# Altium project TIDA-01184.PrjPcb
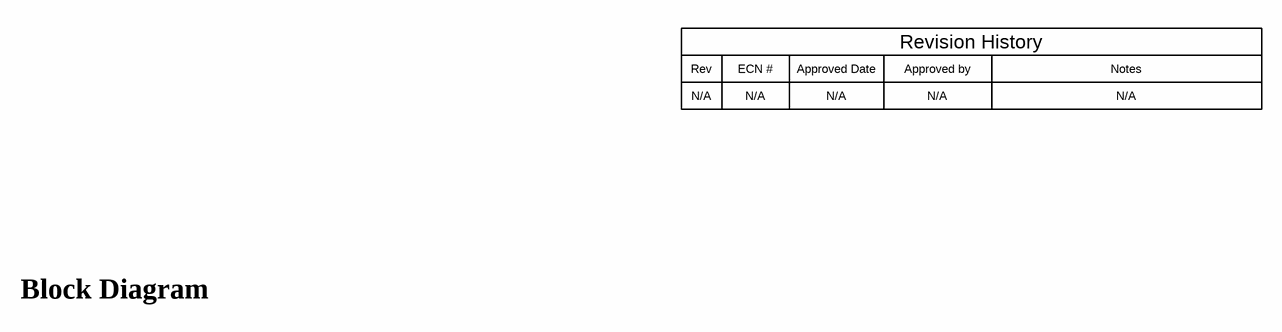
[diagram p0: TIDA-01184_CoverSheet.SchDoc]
CopyrightYear: 2017; PCB_Rev: A; PRJ_Customer: Public Release; PRJ_Engineer: Mitchell Kinkeade; PRJ_Number: TIDA-01184; PRJ_Title: Smart Power Switch Seat Heater Reference Design; SCH_Rev: A; TechSupport: http://www.ti.com/support; TID: TIDA-01184
7 sheets, 128 parts. Net scope: flat (ports and power ports of the same name join across sheets).
Board file: TIDA-01184_Mainboard.PcbDoc
Sheets:
  TIDA-01184_CoverSheet.SchDoc
  TIDA-01184_LED_Drivers.SchDoc
  TIDA-01184_Digital.SchDoc
  TIDA-01184_EVM_Hardware.SchDoc
  TIDA-01184_HighSideDrivers.SchDoc
  TIDA-01184_Load_Card.SchDoc
  TIDA-01184_Power.SchDoc

## Sheet TIDA-01184_CoverSheet.SchDoc
size 431 x 279 mm; Date: Not shown in title block; ApprovedBy: Not shown in title block; CheckedBy: Not shown in title block; Author: Not shown in title block; CompanyName: Not shown in title block; Engineer: Not shown in title block; Organization: Not shown in title block; Address1: Not shown in title block; Address2: Not shown in title block; Address3: Not shown in title block; Address4: Not shown in title block; DocumentNumber: 1; Revision: Use project parameter SCH_Rev; SheetNumber: 1; SheetTotal: 3; PageSetup: Record=PageOptions¦CenterHorizontal=True¦CenterVertical=True¦PrintScale=1.00¦XCorrection=1.00¦YCorrection=1.00¦PrintKind=0¦BorderSize=5000000¦LeftOffset=0¦BottomOffset=0¦Orientation=2¦PaperLength=1000¦PaperWidth=1000¦Scale=100¦PaperSource=15¦PrintQuality=600¦MediaType=1¦DitherType=10¦PaperKind=Letter¦PrintScaleMode=1

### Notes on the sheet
- Rev
- N/A
- ECN #
- Approved Date
- Approved by
- Revision History
- Notes
- Block Diagram

## Sheet TIDA-01184_LED_Drivers.SchDoc
size 431 x 279 mm; Date: Not shown in title block; ApprovedBy: Not shown in title block; CheckedBy: Not shown in title block; Author: Not shown in title block; CompanyName: Not shown in title block; Engineer: Not shown in title block; Organization: Not shown in title block; Address1: Not shown in title block; Address2: Not shown in title block; Address3: Not shown in title block; Address4: Not shown in title block; DocumentNumber: 1; Revision: Use project parameter SCH_Rev; SheetNumber: 2; SheetTotal: 3; PageSetup: Record=PageOptions¦CenterHorizontal=True¦CenterVertical=True¦PrintScale=1.00¦XCorrection=1.00¦YCorrection=1.00¦PrintKind=0¦BorderSize=5000000¦LeftOffset=0¦BottomOffset=0¦Orientation=2¦PaperLength=1000¦PaperWidth=1000¦Scale=100¦PaperSource=15¦PrintQuality=600¦MediaType=1¦DitherType=10¦PaperKind=Letter¦PrintScaleMode=1
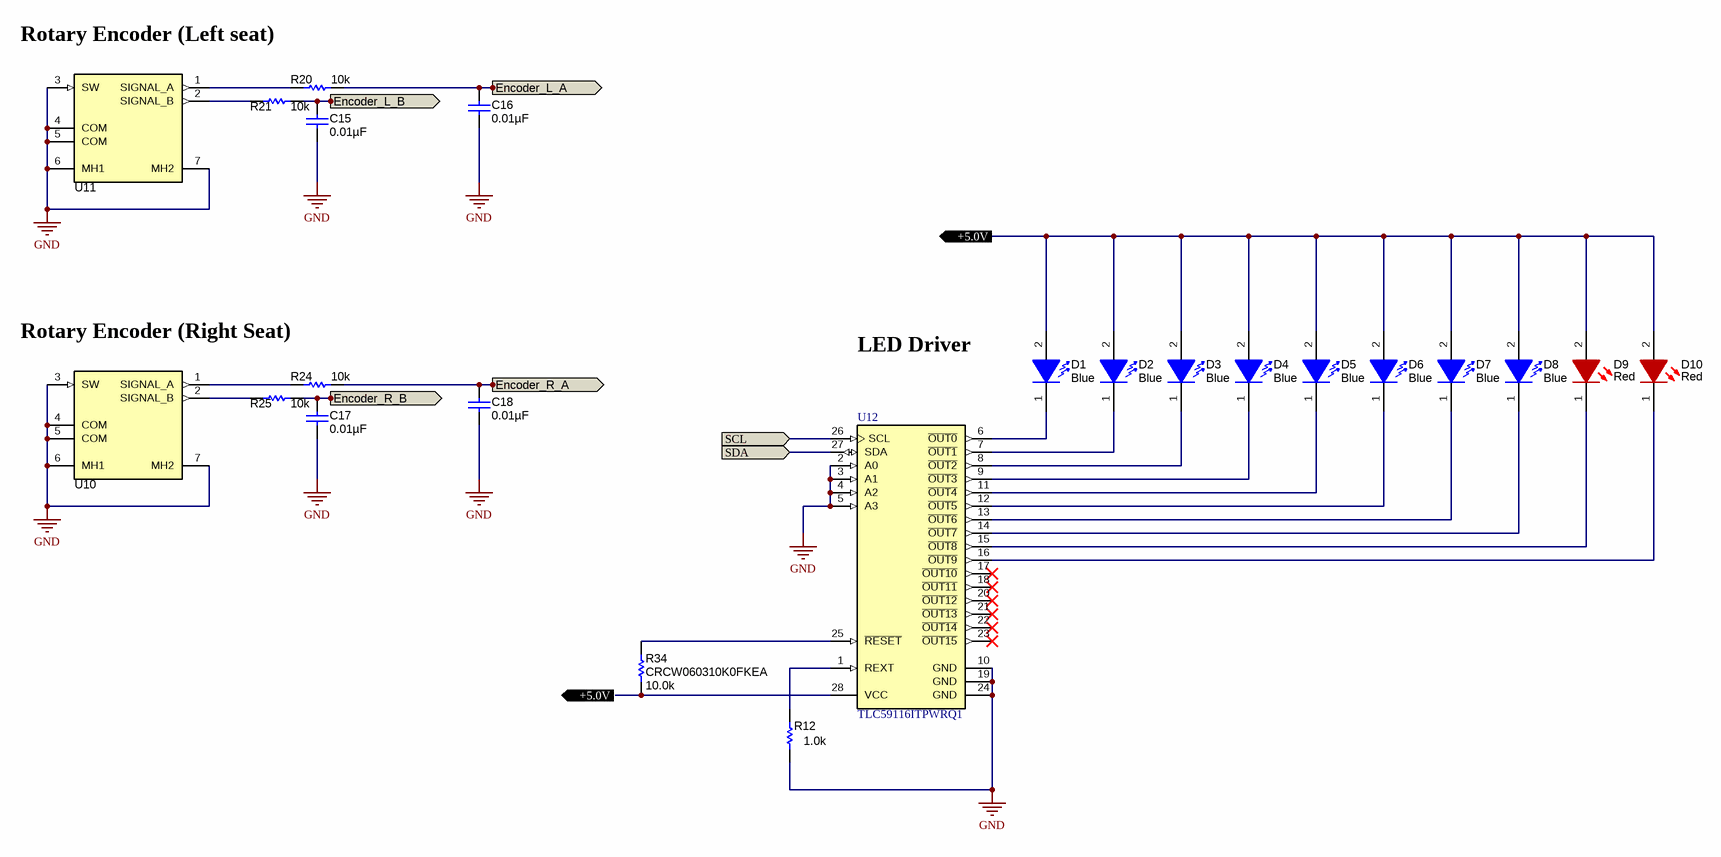
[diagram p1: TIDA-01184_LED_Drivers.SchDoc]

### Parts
C15  ValueDisplayed: 0.01µF  [0805_HV]  (hidden comment: C0805C104M5RACTU)
C16  ValueDisplayed: 0.01µF  [0805_HV]  (hidden comment: C0805C104M5RACTU)
C17  ValueDisplayed: 0.01µF  [0805_HV]  (hidden comment: C0805C104M5RACTU)
C18  ValueDisplayed: 0.01µF  [0805_HV]  (hidden comment: C0805C104M5RACTU)
D1  value Blue  [WL-SMCW_Blue_0805]  (hidden comment: 150080BS75000)
D2  value Blue  [WL-SMCW_Blue_0805]  (hidden comment: 150080BS75000)
D3  value Blue  [WL-SMCW_Blue_0805]  (hidden comment: 150080BS75000)
D4  value Blue  [WL-SMCW_Blue_0805]  (hidden comment: 150080BS75000)
D5  value Blue  [WL-SMCW_Blue_0805]  (hidden comment: 150080BS75000)
D6  value Blue  [WL-SMCW_Blue_0805]  (hidden comment: 150080BS75000)
D7  value Blue  [WL-SMCW_Blue_0805]  (hidden comment: 150080BS75000)
D8  value Blue  [WL-SMCW_Blue_0805]  (hidden comment: 150080BS75000)
D9  value Red  [WL-SMCW_RED_0805]  (hidden comment: 150080SS75000)
D10  value Red  [WL-SMCW_RED_0805]  (hidden comment: 150080SS75000)
R12  ValueDisplayed: 1.0k  [0603]  (hidden comment: RC0603JR-071KL)
R20  ValueDisplayed: 10k  [0603]  (hidden comment: CRCW060310K0JNEA)
R21  ValueDisplayed: 10k  [0603]  (hidden comment: CRCW060310K0JNEA)
R24  ValueDisplayed: 10k  [0603]  (hidden comment: CRCW060310K0JNEA)
R25  ValueDisplayed: 10k  [0603]  (hidden comment: CRCW060310K0JNEA)
R34  CRCW060310K0FKEA  ValueDisplayed: 10.0k  [0603]
U10  EVE-JBBF2020B  [Panasonic_EVE-JBBF2020B]  (value not drawn)
U11  EVE-JBBF2020B  [Panasonic_EVE-JBBF2020B]  (value not drawn)
U12  TLC59116ITPWRQ1  [PW0028A_N]

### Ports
+5.0V, Encoder_L_A (out), Encoder_L_B (out), Encoder_R_A (out), Encoder_R_B (out), SCL, SDA

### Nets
GND: C15.2 C16.2 C17.2 C18.2 R12.1 U10.3(SW) U10.4(COM) U10.5(COM) U10.6(MH1) U10.7(MH2) U11.3(SW) U11.4(COM) U11.5(COM) U11.6(MH1) U11.7(MH2) U12.2(A0) U12.3(A1) U12.4(A2) U12.5(A3) U12.10(GND) U12.19(GND) U12.24(GND)
+5.0V: D1.2(A) D2.2(A) D3.2(A) D4.2(A) D5.2(A) D6.2(A) D7.2(A) D8.2(A) D9.2(A) D10.2(A) R34.1 U12.28(VCC) ; port +5.0V
Encoder_L_A: C16.1 R20.2 ; port Encoder_L_A
Encoder_L_B: C15.1 R21.2 ; port Encoder_L_B
Encoder_R_A: C18.1 R24.2 ; port Encoder_R_A
Encoder_R_B: C17.1 R25.2 ; port Encoder_R_B
SCL: U12.26(SCL) ; port SCL
SDA: U12.27(SDA) ; port SDA
NetD1_1: D1.1(K) U12.6(~{OUT0})
NetD2_1: D2.1(K) U12.7(~{OUT1})
NetD3_1: D3.1(K) U12.8(~{OUT2})
NetD4_1: D4.1(K) U12.9(~{OUT3})
NetD5_1: D5.1(K) U12.11(~{OUT4})
NetD6_1: D6.1(K) U12.12(~{OUT5})
NetD7_1: D7.1(K) U12.13(~{OUT6})
NetD8_1: D8.1(K) U12.14(~{OUT7})
NetD9_1: D9.1(K) U12.15(~{OUT8})
NetD10_1: D10.1(K) U12.16(~{OUT9})
NetR12_2: R12.2 U12.1(REXT)
NetR20_1: R20.1 U11.1(SIGNAL_A)
NetR21_1: R21.1 U11.2(SIGNAL_B)
NetR24_1: R24.1 U10.1(SIGNAL_A)
NetR25_1: R25.1 U10.2(SIGNAL_B)
NetR34_2: R34.2 U12.25(~{RESET})

Not connected (* = marked no-connect by the designer): U12 17(~{OUT10})* 18(~{OUT11})* 20(~{OUT12})* 21(~{OUT13})* 22(~{OUT14})* 23(~{OUT15})*

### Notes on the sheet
- Rotary Encoder (Left seat)
- Rotary Encoder (Right Seat)
- LED Driver

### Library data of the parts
C15-C18 = C0805C104M5RACTU: CAP, CERM, 0.1 µF, 50 V, +/- 20%, X7R, 0805; Manufacturer: Kemet; Polarized: N; CompType: Capacitor; Value: 0.1uF; U/M: EA; Cap_F: 0.0000001; Tolerance_%: 20; ESR_ohm: 0.064; Value1: 0.064 ohm; VDC_V: 50; Value2: 50V; IRMS_A: 1.64; TaMin_C: -55; TaMax_C: 125; Cap_Case: 0805; SizeArea_mm2: 2.5; SizeAreaWB_mm2: 6.75; SizeX_mm: 2; SizeY_mm: 1.25; SizeZ_mm: 1.45; AEC Category: Q200
D1-D8 = 150080BS75000: LED, Blue, SMD; Manufacturer: Wurth Elektronik; Type: InGaN; Vf_V: 3.2; Value2: 3.2V; Io_A: 0.02; Vr_V: 5; Tjmax_C: 85; Power_TotalModule: 0.105; Value1: 0.105W; Angle: 140; U/M: EA
D9 D10 = 150080SS75000: LED, Red, SMD; Manufacturer: Wurth Elektronik; SymbolCreator: Altium; Type: AlInGaP; Vf_V: 1.9; Value2: 1.9V; Io_A: 0.03; Vr_V: 5; Ir_A: 2.5e-005; Tjmax_C: 85; Power_TotalModule: 0.072; Value1: 0.072W; Angle: 140; U/M: EA
R12 = RC0603JR-071KL: RES, 1.0 k, 5%, 0.1 W, 0603; Manufacturer: Yageo America; CompType: Resistor; Value: 1.0k; Res_ohm: 1000; Value_Code: 1k00; Tolerance_%: 5; Power_W: 0.1; Value2: 0.1W; VDC_V: 50; TempCo: 100 ppm/C; EIA_Code: E24; U/M: EA
R20 R21 R24 R25 = CRCW060310K0JNEA: RES, 10 k, 5%, 0.1 W, 0603; Manufacturer: Vishay-Dale; CompType: Resistor; Value: 10k; Res_ohm: 10000; Value_Code: 10k0; Tolerance_%: 5; Power_W: 0.1; Value2: 0.1W; VDC_V: 75; TempCo: 200 ppm/C; EIA_Code: E24; U/M: EA
R34 = CRCW060310K0FKEA: RES, 10.0 k, 1%, 0.1 W, 0603; Manufacturer: Vishay-Dale; CompType: Resistor; Value: 10.0k; Res_ohm: 10000; Value_Code: 10k0; Tolerance_%: 1; Power_W: 0.1; Value2: 0.1W; VDC_V: 75; TempCo: 100 ppm/C; SizeArea_mm2: 1.28; SizeX_mm: 1.6; SizeY_mm: 0.8; EIA_Code: E96; U/M: EA; AEC Category: Q200
U10 U11 = EVE-JBBF2020B: ENCODER ROTARY 12MM 20PPR W/SW, TH; Manufacturer: Panasonic; SymbolCreator: Altium
U12 = TLC59116IPWR: 16-Bit Fast-Mode Plus (FM+) I2C Bus Constant-Current LED Sink Driver, 3 to 5.5 V, -40 to 85 degC, 28-pin SOP (PW28), Green (RoHS & no Sb/Br); Manufacturer: Texas Instruments; Alternate PartNumber: Equivalent; Rating: Catalog; SubFamily: LED Driver; Vin(Max)(V): 5.5; Vin(Min)(V): 3

## Sheet TIDA-01184_Digital.SchDoc
size 431 x 279 mm; Date: Not shown in title block; ApprovedBy: Not shown in title block; CheckedBy: Not shown in title block; Author: Not shown in title block; CompanyName: Not shown in title block; DrawnBy: Mitchell Kinkeade; Engineer: Not shown in title block; Organization: Not shown in title block; Address1: Not shown in title block; Address2: Not shown in title block; Address3: Not shown in title block; Address4: Not shown in title block; DocumentNumber: 1; Revision: Use project parameter SCH_Rev; SheetNumber: 2; SheetTotal: 3; PageSetup: Record=PageOptions¦CenterHorizontal=True¦CenterVertical=True¦PrintScale=1.00¦XCorrection=1.00¦YCorrection=1.00¦PrintKind=0¦BorderSize=5000000¦LeftOffset=0¦BottomOffset=0¦Orientation=2¦PaperLength=1000¦PaperWidth=1000¦Scale=100¦PaperSource=15¦PrintQuality=600¦MediaType=1¦DitherType=10¦PaperKind=Letter¦PrintScaleMode=1
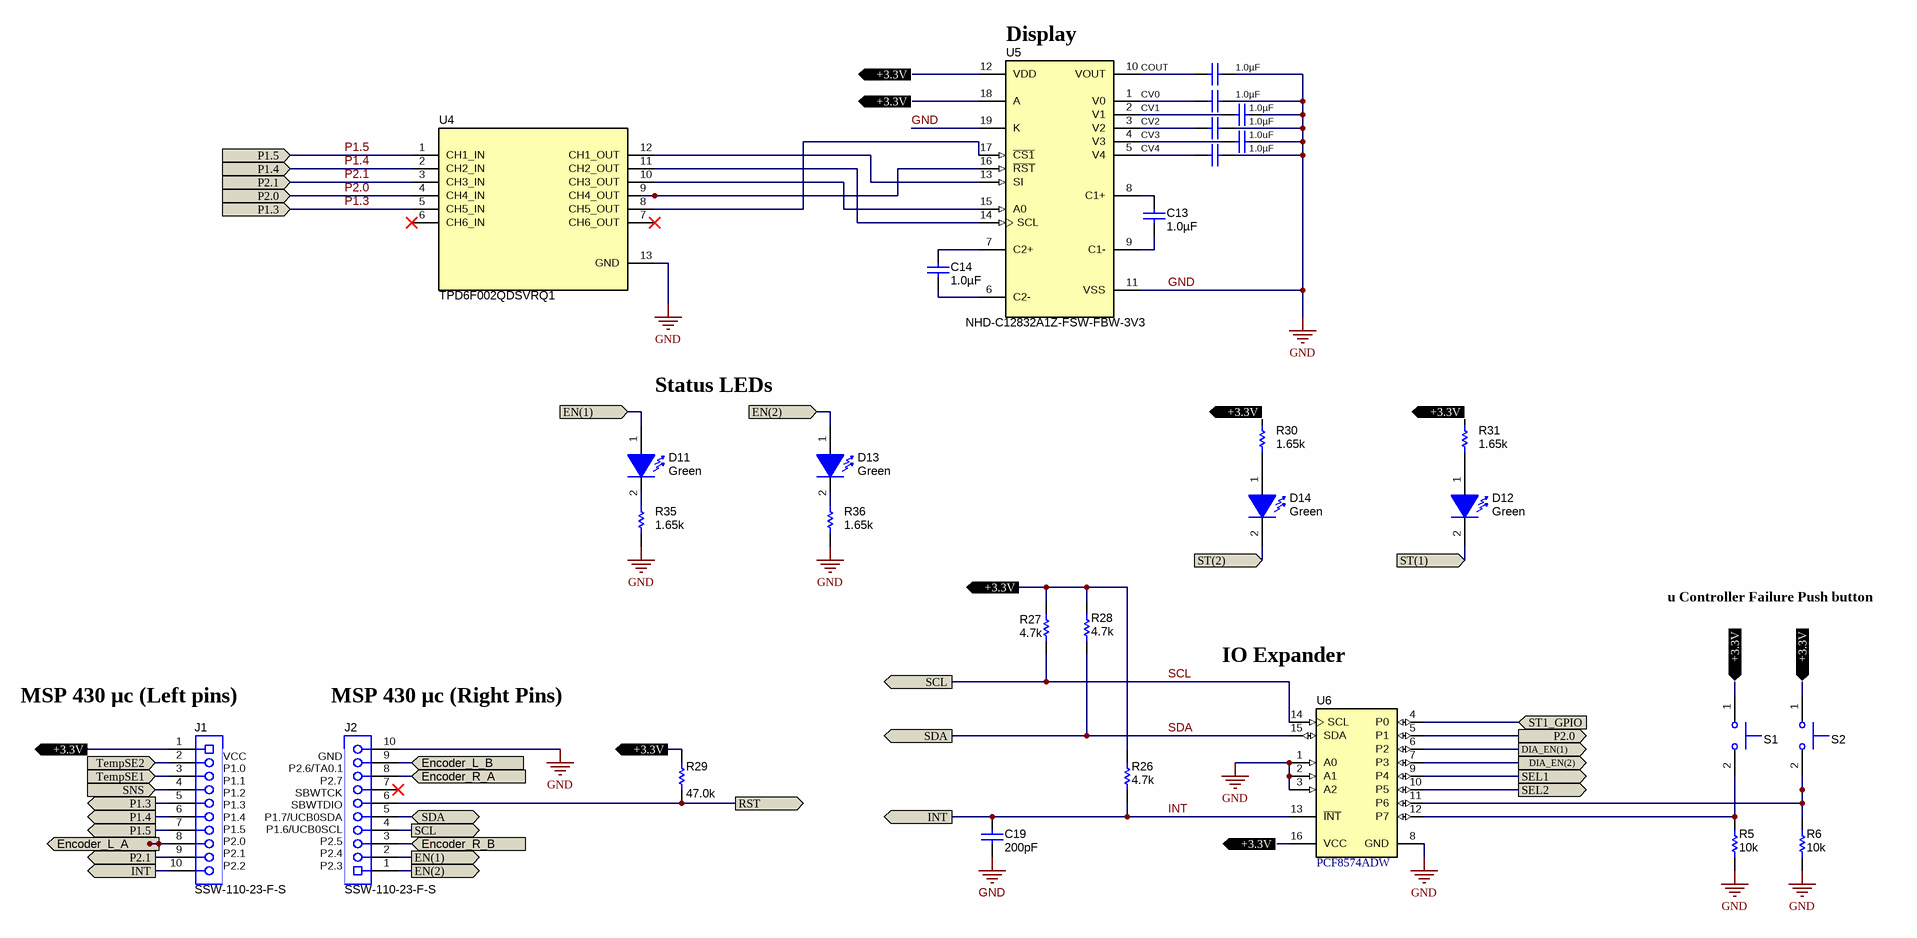
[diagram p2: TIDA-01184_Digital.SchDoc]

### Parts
C13  ValueDisplayed: 1.0µF  [0805_HV]  (hidden comment: C0805C104M5RACTU)
C14  ValueDisplayed: 1.0µF  [0805_HV]  (hidden comment: C0805C104M5RACTU)
C19  ValueDisplayed: 200pF  [0805_HV]  (hidden comment: C0805C104M5RACTU)
COUT  ValueDisplayed: 1.0µF  [0805_HV]  (hidden comment: C0805C104M5RACTU)
CV0  ValueDisplayed: 1.0µF  [0805_HV]  (hidden comment: C0805C104M5RACTU)
CV1  ValueDisplayed: 1.0µF  [0805_HV]  (hidden comment: C0805C104M5RACTU)
CV2  ValueDisplayed: 1.0µF  [0805_HV]  (hidden comment: C0805C104M5RACTU)
CV3  ValueDisplayed: 1.0uF  [0805_HV]  (hidden comment: C0805C104M5RACTU)
CV4  ValueDisplayed: 1.0µF  [0805_HV]  (hidden comment: C0805C104M5RACTU)
D11  value Green  [LG L29K_GREEN]  (hidden comment: LG L29K-G2J1-24-Z)
D12  value Green  [LG L29K_GREEN]  (hidden comment: LG L29K-G2J1-24-Z)
D13  value Green  [LG L29K_GREEN]  (hidden comment: LG L29K-G2J1-24-Z)
D14  value Green  [LG L29K_GREEN]  (hidden comment: LG L29K-G2J1-24-Z)
J1  SSW-110-23-F-S  [CONN_SSW-110-23-F-S]
J2  SSW-110-23-F-S  [CONN_SSW-110-23-F-S]
R5  ValueDisplayed: 10k  [0603]  (hidden comment: RC0603JR-071KL)
R6  ValueDisplayed: 10k  [0603]  (hidden comment: RC0603JR-071KL)
R26  ValueDisplayed: 4.7k  [0603]  (hidden comment: CRCW060310K0JNEA)
R27  ValueDisplayed: 4.7k  [0603]  (hidden comment: CRCW060310K0JNEA)
R28  ValueDisplayed: 4.7k  [0603]  (hidden comment: CRCW060310K0JNEA)
R29  ValueDisplayed: 47.0k  [0603]  (hidden comment: RC0603FR-0747KL)
R30  ValueDisplayed: 1.65k  [0603]  (hidden comment: RC0603FR-071K65L)
R31  ValueDisplayed: 1.65k  [0603]  (hidden comment: RC0603FR-071K65L)
R35  ValueDisplayed: 1.65k  [0603]  (hidden comment: RC0603FR-071K65L)
R36  ValueDisplayed: 1.65k  [0603]  (hidden comment: RC0603FR-071K65L)
S1  SKRKAEE010  [SW_SKRKAEE010]  (value not drawn)
S2  SKRKAEE010  [SW_SKRKAEE010]  (value not drawn)
U4  TPD6F002QDSVRQ1  [DSV0012A]
U5  NHD-C12832A1Z-FSW-FBW-3V3  [NHD-C12832A1Z-FSW-FBW-3V3]
U6  PCF8574ADW  [DW0016A_N]

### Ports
+3.3V, DIA_EN(1) (out), DIA_EN(2) (out), EN(1), EN(1) (out), EN(2), EN(2) (out), Encoder_L_A (in), Encoder_L_B (in), Encoder_R_A (in), Encoder_R_B (in), INT, P1.3 (in), P1.3 (out), P1.4 (in), P1.4 (out), P1.5 (in), P1.5 (out), P2.0 (in), P2.0 (out), P2.1 (in), P2.1 (out), RST, SCL, SCL (out), SDA, SDA (bidir), SEL1 (out), SEL2 (out), SNS (in), ST1_GPIO (in), ST(1), ST(2), TempSE1 (in), TempSE2 (in)

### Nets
GND: C19.1 COUT.1 CV0.1 CV1.1 CV2.1 CV3.1 CV4.1 J2.10 R5.2 R6.2 R35.1 R36.1 U4.13(GND) U5.11(VSS) U5.19(K) U6.1(A0) U6.2(A1) U6.3(A2) U6.8(GND)
+3.3V: J1.1 R26.2 R27.2 R28.2 R29.2 R30.2 R31.2 S1.1 S2.1 U5.12(VDD) U5.18(A) U6.16(VCC) ; port +3.3V
DIA_EN(1): U6.6(P2) ; port DIA_EN(1)
DIA_EN(2): U6.7(P3) ; port DIA_EN(2)
EN(1): D11.1(A) J2.2 ; port EN(1)
EN(2): D13.1(A) J2.1 ; port EN(2)
Encoder_L_A: J1.8 ; port Encoder_L_A
Encoder_L_B: J2.9 ; port Encoder_L_B
Encoder_R_A: J2.8 ; port Encoder_R_A
Encoder_R_B: J2.3 ; port Encoder_R_B
INT: C19.2 J1.10 R26.1 U6.13(~{INT}) ; port INT
P1.3: J1.5 U4.5(CH5_IN) ; port P1.3
P1.4: J1.6 U4.2(CH2_IN) ; port P1.4
P1.5: J1.7 U4.1(CH1_IN) ; port P1.5
P2.0: U4.4(CH4_IN) U6.5(P1) ; port P2.0
P2.1: J1.9 U4.3(CH3_IN) ; port P2.1
RST: J2.6 R29.1 ; port RST
SCL: J2.4 R27.1 U6.14(SCL) ; port SCL
SDA: J2.5 R28.1 U6.15(SDA) ; port SDA
SEL_1(1): U6.9(P4) ; port SEL1
SEL_2(1): U6.10(P5) ; port SEL2
SNS: J1.4 ; port SNS
ST(1): D12.2(K) U6.4(P0) ; port ST(1), port ST1_GPIO
ST(2): D14.2(K) ; port ST(2)
TempSE1: J1.3 ; port TempSE1
TempSE2: J1.2 ; port TempSE2
NetC13_1: C13.1 U5.8(C1+)
NetC13_2: C13.2 U5.9(C1-)
NetC14_1: C14.1 U5.7(C2+)
NetC14_2: C14.2 U5.6(C2-)
NetCOUT_2: COUT.2 U5.10(VOUT)
NetCV0_2: CV0.2 U5.1(V0)
NetCV1_2: CV1.2 U5.2(V1)
NetCV2_2: CV2.2 U5.3(V2)
NetCV3_2: CV3.2 U5.4(V3)
NetCV4_2: CV4.2 U5.5(V4)
NetD11_2: D11.2(K) R35.2
NetD12_1: D12.1(A) R31.1
NetD13_2: D13.2(K) R36.2
NetD14_1: D14.1(A) R30.1
NetR5_1: R5.1 S1.2 U6.12(P7)
NetR6_1: R6.1 S2.2 U6.11(P6)
NetU4_8: U4.8(CH5_OUT) U5.17(~{CS1})
NetU4_9: U4.9(CH4_OUT) U5.16(~{RST})
NetU4_10: U4.10(CH3_OUT) U5.15(A0)
NetU4_11: U4.11(CH2_OUT) U5.14(SCL)
NetU4_12: U4.12(CH1_OUT) U5.13(SI)

Not connected (* = marked no-connect by the designer): J2 7*; U4 6(CH6_IN)* 7(CH6_OUT)*

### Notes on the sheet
- (near U5) Display
- Status LEDs
- u Controller Failure Push button
- (near J1) MSP 430 µc (Left pins)
- (near J2) MSP 430 µc (Right Pins)
- IO Expander
- (near J1) VCC
  P1.0
  P1.1
  P1.2
  P1.3
  P1.4
  P1.5
  P2.0
  P2.1
  P2.2
- (near J2) GND
  P2.6/TA0.1
  P2.7
  SBWTCK
  SBWTDIO
  P1.7/UCB0SDA
  P1.6/UCB0SCL
  P2.5
  P2.4
  P2.3

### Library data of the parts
C13 C14 C19 COUT CV0-CV4 = C0805C104M5RACTU: as C15 on sheet TIDA-01184_LED_Drivers
D11-D14 = LG L29K-G2J1-24-Z: LED, Green, SMD; Manufacturer: OSRAM; Vf_V: 1.7; Value2: 1.7V; Io_A: 0.002; Tjmax_C: 110; Value1: W; U/M: EA
J1 J2 = SSW-110-23-F-S: Connector, Receptacle, 100mil, 10x1, Gold plated, TH; Manufacturer: Samtec; SymbolCreator: a0411947
R5 R6 = RC0603JR-071KL: as R12 on sheet TIDA-01184_LED_Drivers
R26-R28 = CRCW060310K0JNEA: as R20 on sheet TIDA-01184_LED_Drivers
R29 = RC0603FR-0747KL: RES, 47.0 k, 1%, 0.1 W, 0603; Manufacturer: Yageo America; CompType: Resistor; Value: 47.0k; Res_ohm: 47000; Value_Code: 47k0; Tolerance_%: 1; Power_W: 0.1; Value2: 0.1W; VDC_V: 150; TempCo: 200 ppm/C; SizeArea_mm2: 1.28; SizeX_mm: 1.6; SizeY_mm: 0.8; U/M: EA; AEC Category: Q200
R30 R31 R35 R36 = RC0603FR-071K65L: RES, 1.65 k, 1%, 0.1 W, 0603; Manufacturer: Yageo America; CompType: Resistor; Value: 1.65k; Res_ohm: 1650; Value_Code: 1k65; Tolerance_%: 1; Power_W: 0.1; Value2: 0.1W; VDC_V: 150; TempCo: 200 ppm/C; SizeArea_mm2: 1.28; SizeX_mm: 1.6; SizeY_mm: 0.8; EIA_Code: E96; U/M: EA; AEC Category: Q200
S1 S2 = SKRKAEE010: Switch, Push Button, SMD; Manufacturer: Alps; SymbolCreator: a0412235; Circuit: SPST-NO; VDC_V: 12; SwitchFunction: Off-Mom; PositionCount: 1; CurrentRating_mA: 50
U4 = TPD6F002QDSVRQ1: Six-Channel EMI Filter for LCD Display / Keypad Application, DSV0012A; Manufacturer: Texas Instruments; SymbolCreator: Altium; SizeArea_mm2: 4.05; SizeAreaWB_mm2: 9.4; SizeX_mm: 1.35; SizeY_mm: 3; SizeZ_mm: 0.8; CompType: IC; U/M: EA
U5 = NHD-C12832A1Z-FSW-FBW-3V3: COG Liquid Crystal Display Module, White LED Backlight 3V, SPI I/O, TH; Manufacturer: Newhaven Display International; SymbolCreator: Altium
U6 = PCF8574ADW: Remote 8-Bit I/O Expander for I2C-Bus, 2.5 to 6.0 V, -40 to 85 degC, 16-pin SOIC (DW), Green (RoHS & no Sb/Br); Manufacturer: Texas Instruments; Alternate PartNumber: Equivalent; SubFamily: I2C IO Expander; Voltage Nodes(V): 5, 3.3; Interrupt Output: Yes; fSCLK(Max)(MHz): 0.1; VCC(Min)(V): 2.5; VCC(Max)(V): 6; Max Frequency(kHz): 100; I2C Address: 0111 xxx; # of I/Os: 8

## Sheet TIDA-01184_EVM_Hardware.SchDoc
size 431 x 279 mm; Date: Not shown in title block; ApprovedBy: Not shown in title block; CheckedBy: Not shown in title block; Author: Not shown in title block; CompanyName: Not shown in title block; Engineer: Not shown in title block; Organization: Not shown in title block; Address1: Not shown in title block; Address2: Not shown in title block; Address3: Not shown in title block; Address4: Not shown in title block; DocumentNumber: 1; Revision: Use project parameter SCH_Rev; SheetNumber: 3; SheetTotal: 3; PageSetup: Record=PageOptions¦CenterHorizontal=True¦CenterVertical=True¦PrintScale=1.00¦XCorrection=1.00¦YCorrection=1.00¦PrintKind=0¦BorderSize=5000000¦LeftOffset=0¦BottomOffset=0¦Orientation=2¦PaperLength=1000¦PaperWidth=1000¦Scale=100¦PaperSource=15¦PrintQuality=600¦MediaType=1¦DitherType=10¦PaperKind=Letter¦PrintScaleMode=1
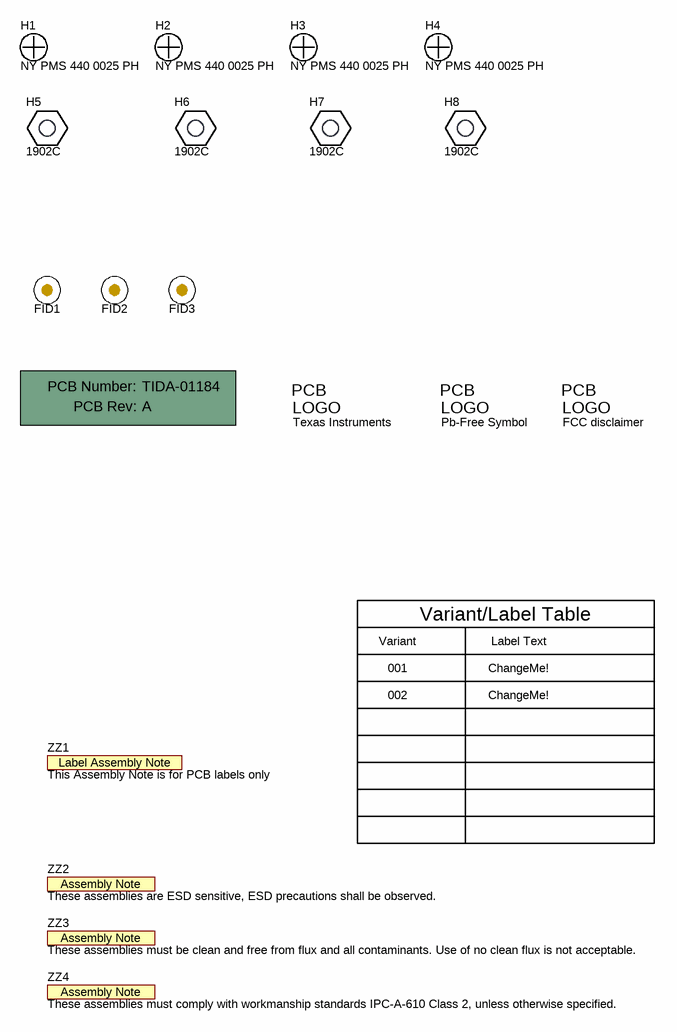
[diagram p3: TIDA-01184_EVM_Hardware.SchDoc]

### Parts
!PCB  Printed Circuit Board  (value not drawn)  (mechanical)
FID1  Fiducial  [Fiducial10-20]  (value not drawn)
FID2  Fiducial  [Fiducial10-20]  (value not drawn)
FID3  Fiducial  [Fiducial10-20]  (value not drawn)
H1  NY PMS 440 0025 PH  [NY PMS 440 0025 PH]
H2  NY PMS 440 0025 PH  [NY PMS 440 0025 PH]
H3  NY PMS 440 0025 PH  [NY PMS 440 0025 PH]
H4  NY PMS 440 0025 PH  [NY PMS 440 0025 PH]
H5  1902C  [Keystone_1902C]
H6  1902C  [Keystone_1902C]
H7  1902C  [Keystone_1902C]
H8  1902C  [Keystone_1902C]
Logo1  Texas Instruments  [TI_Stacked_Overlay_Small]  (no BOM)
Logo2  Pb-Free Symbol  [Pb-Free_Overlay_Small]  (no BOM)
Logo3  FCC disclaimer  [FCC_disclaimer]  (no BOM)
ZZ1  This Assembly Note is for PCB labels only  [AssemblyNoteLabel]  (no BOM)
ZZ2  These assemblies are ESD sensitive, ESD precautions shall be observed.  [AssemblyNote]  (no BOM)
ZZ3  These assemblies must be clean and free from flux and all contaminants. Use of no clean flux is not acceptable.  [AssemblyNote]  (no BOM)
ZZ4  These assemblies must comply with workmanship standards IPC-A-610 Class 2, unless otherwise specified.  [AssemblyNote]  (no BOM)

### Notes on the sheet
- Variant
- Variant/Label Table
- Label Text
- 001
- 002
- ChangeMe!

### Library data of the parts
!PCB = PCB: Manufacturer: Any; PartNumber: TIDA-01184; SymbolCreator: a0412235
FID1-FID3 = Fiducial: Fiducial mark.  There is nothing to buy or mount.; SymbolCreator: codlsc
H1-H4 = NY PMS 440 0025 PH: Machine Screw, Round, #4-40 x 1/4, Nylon, Philips panhead; Manufacturer: B&F Fastener Supply; CompType: Hardware; SymbolCreator: codlsc; U/M: EA
H5-H8 = 1902C: Standoff, Hex, 0.5"L #4-40 Nylon; Manufacturer: Keystone; CompType: Hardware
Logo1 = TI_Logo: Texas Instrument Corporate Signature; SymbolCreator: codlsc
Logo2 = Pb-Free: SymbolCreator: a0412235
Logo3 = FCC_disclaimer: SymbolCreator: codlsc
ZZ1 = AssemblyNoteLabel: SymbolCreator: a0412235
ZZ2-ZZ4 = AssemblyNote: SymbolCreator: codlsc

## Sheet TIDA-01184_HighSideDrivers.SchDoc
size 431 x 279 mm; Date: Not shown in title block; ApprovedBy: Not shown in title block; CheckedBy: Not shown in title block; Author: Not shown in title block; CompanyName: Not shown in title block; Engineer: Not shown in title block; Organization: Not shown in title block; Address1: Not shown in title block; Address2: Not shown in title block; Address3: Not shown in title block; Address4: Not shown in title block; DocumentNumber: 1; Revision: Use project parameter SCH_Rev; SheetNumber: 2; SheetTotal: 3; PageSetup: Record=PageOptions¦CenterHorizontal=True¦CenterVertical=True¦PrintScale=1.00¦XCorrection=1.00¦YCorrection=1.00¦PrintKind=0¦BorderSize=5000000¦LeftOffset=0¦BottomOffset=0¦Orientation=2¦PaperLength=1000¦PaperWidth=1000¦Scale=100¦PaperSource=15¦PrintQuality=-3¦MediaType=1¦DitherType=10¦PrintScaleMode=1¦PaperKind=Letter¦PaperIndex=1
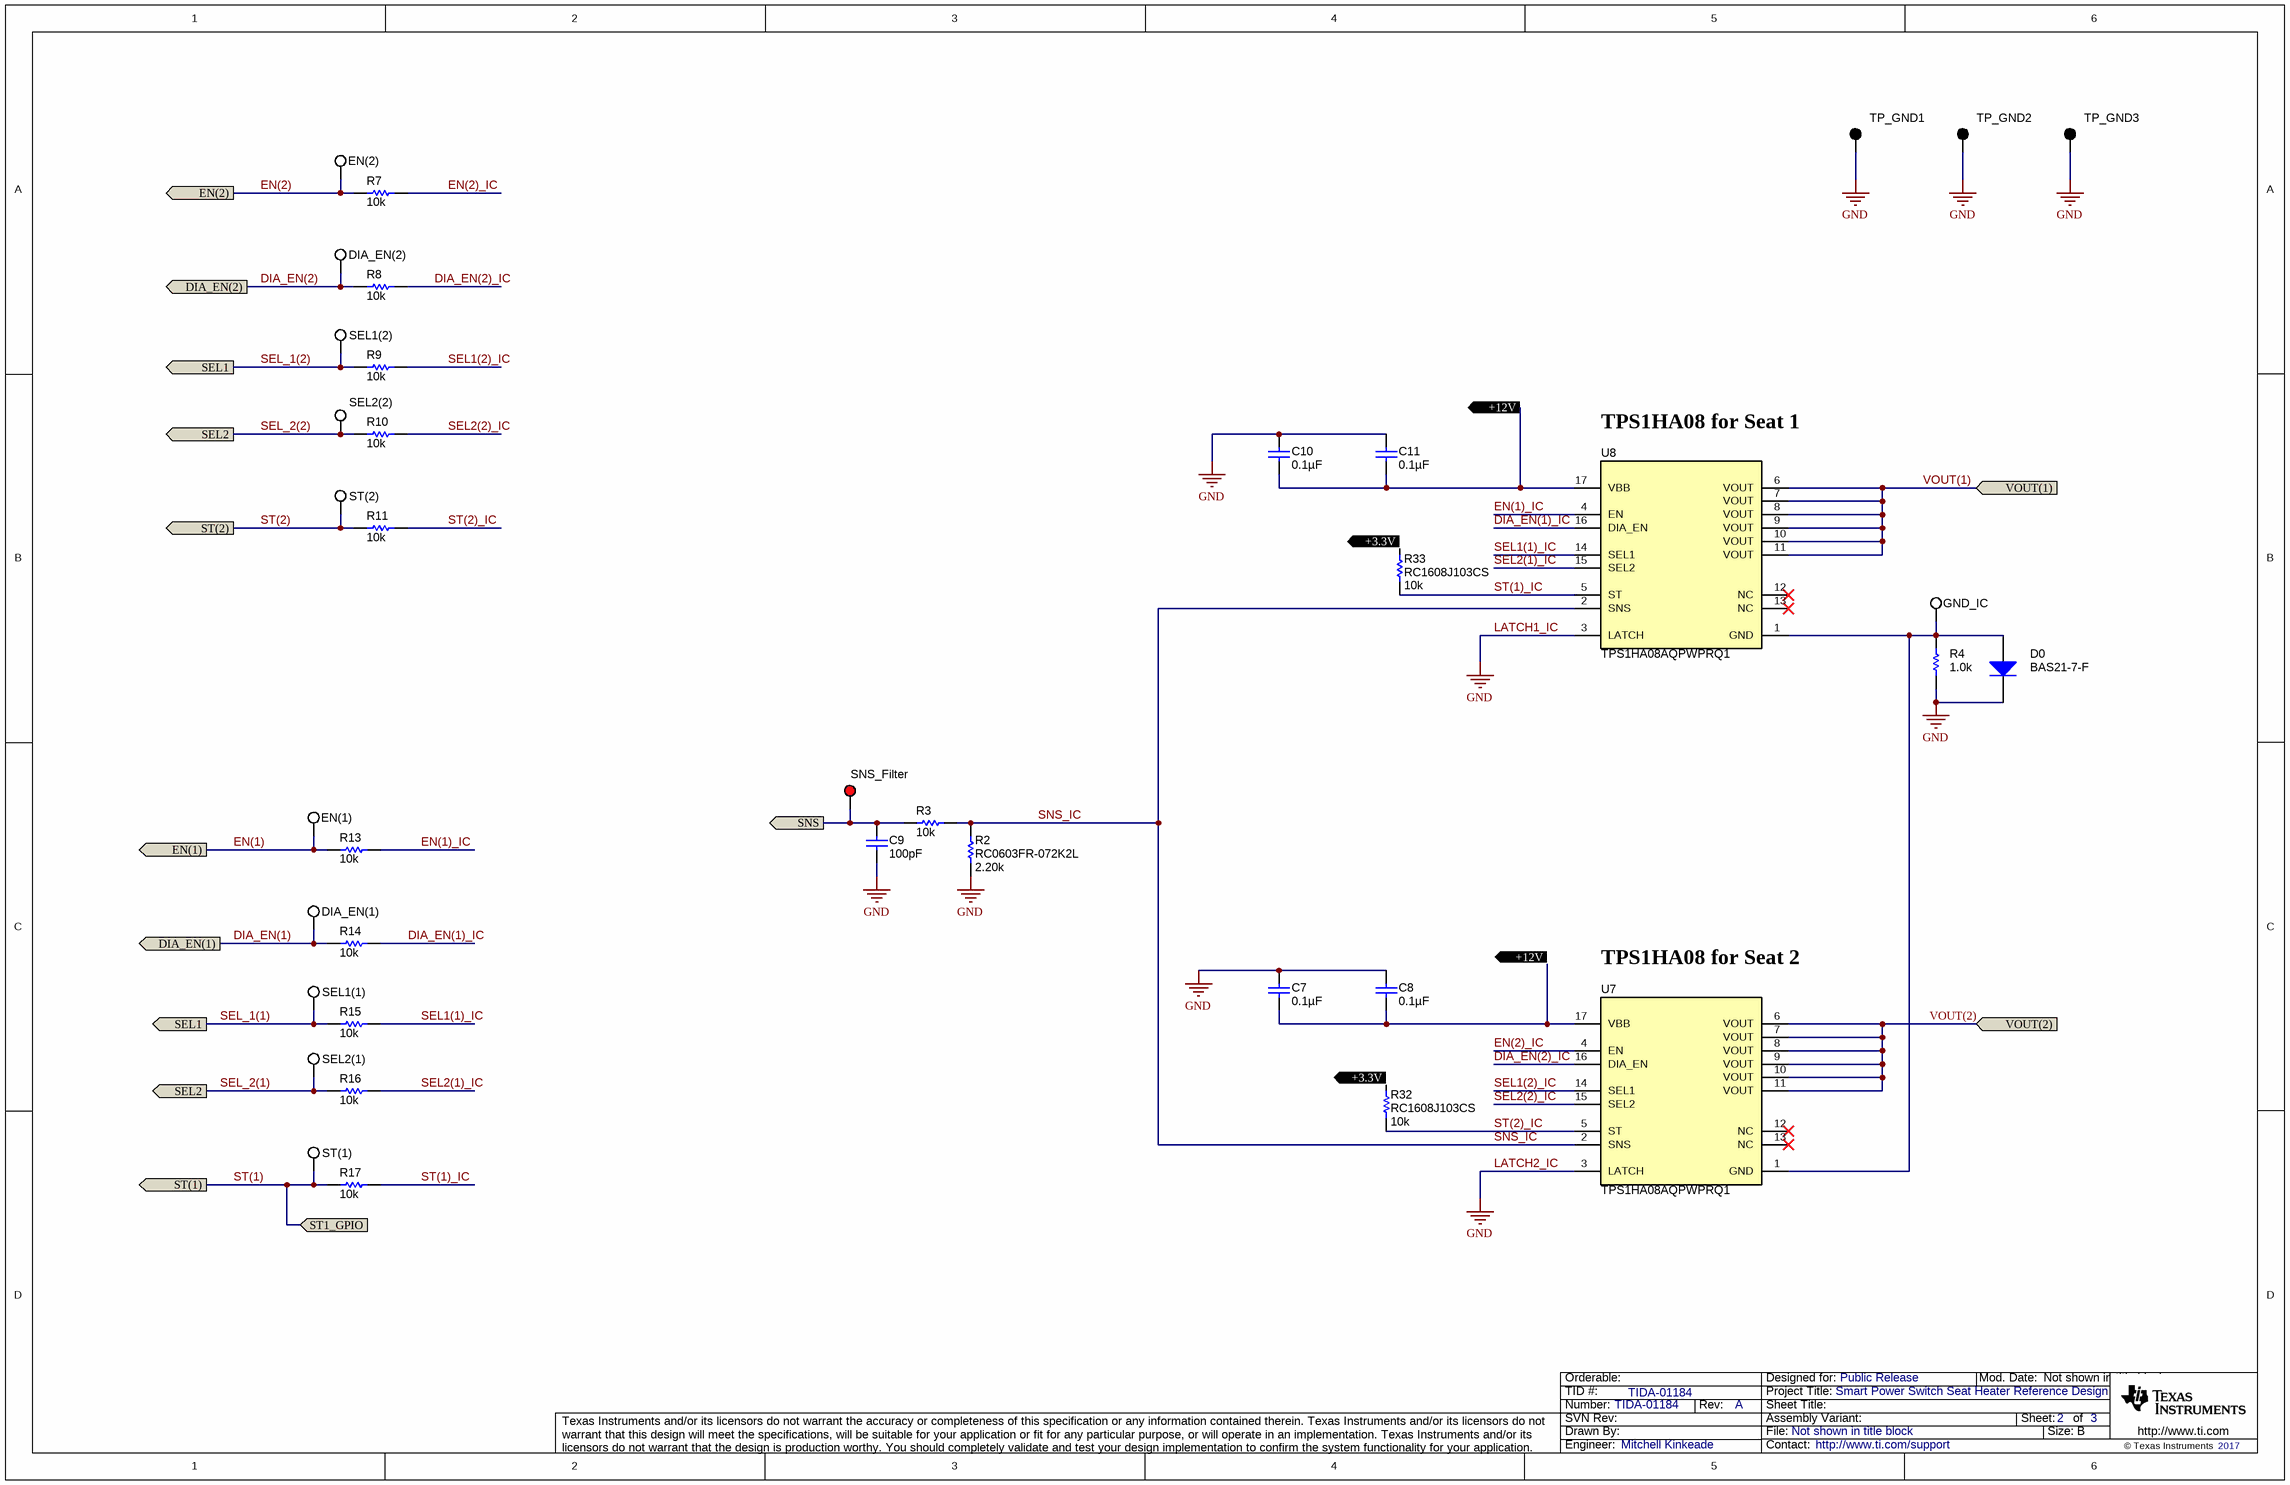
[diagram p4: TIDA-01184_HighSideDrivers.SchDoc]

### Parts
C7  ValueDisplayed: 0.1µF  [0805_HV]  (hidden comment: C0805C104M5RACTU)
C8  ValueDisplayed: 0.1µF  [0805_HV]  (hidden comment: C0805C104M5RACTU)
C9  ValueDisplayed: 100pF  [0805_HV]  (hidden comment: C0805C104M5RACTU)
C10  ValueDisplayed: 0.1µF  [0805_HV]  (hidden comment: C0805C104M5RACTU)
C11  ValueDisplayed: 0.1µF  [0805_HV]  (hidden comment: C0805C104M5RACTU)
D0  BAS21-7-F  [SOT-23]
DIA_EN(1)  5002  [Keystone5002]  (value not drawn)
DIA_EN(2)  5002  [Keystone5002]  (value not drawn)
EN(1)  5002  [Keystone5002]  (value not drawn)
EN(2)  5002  [Keystone5002]  (value not drawn)
GND_IC  5002  [Keystone5002]  (value not drawn)
R2  RC0603FR-072K2L  ValueDisplayed: 2.20k  [0603]
R3  ValueDisplayed: 10k  [0603]  (hidden comment: CRCW060310K0JNEA)
R4  ValueDisplayed: 1.0k  [0603]  (hidden comment: RC0603JR-071KL)
R7  ValueDisplayed: 10k  [0603]  (hidden comment: CRCW060310K0JNEA)
R8  ValueDisplayed: 10k  [0603]  (hidden comment: CRCW060310K0JNEA)
R9  ValueDisplayed: 10k  [0603]  (hidden comment: CRCW060310K0JNEA)
R10  ValueDisplayed: 10k  [0603]  (hidden comment: CRCW060310K0JNEA)
R11  ValueDisplayed: 10k  [0603]  (hidden comment: CRCW060310K0JNEA)
R13  ValueDisplayed: 10k  [0603]  (hidden comment: CRCW060310K0JNEA)
R14  ValueDisplayed: 10k  [0603]  (hidden comment: CRCW060310K0JNEA)
R15  ValueDisplayed: 10k  [0603]  (hidden comment: CRCW060310K0JNEA)
R16  ValueDisplayed: 10k  [0603]  (hidden comment: CRCW060310K0JNEA)
R17  ValueDisplayed: 10k  [0603]  (hidden comment: CRCW060310K0JNEA)
R32  RC1608J103CS  ValueDisplayed: 10k  [0603]
R33  RC1608J103CS  ValueDisplayed: 10k  [0603]
SEL1(1)  5002  [Keystone5002]  (value not drawn)
SEL1(2)  5002  [Keystone5002]  (value not drawn)
SEL2(1)  5002  [Keystone5002]  (value not drawn)
SEL2(2)  5002  [Keystone5002]  (value not drawn)
SNS_Filter  5010  [Keystone5010]  (value not drawn)
ST(1)  5002  [Keystone5002]  (value not drawn)
ST(2)  5002  [Keystone5002]  (value not drawn)
TP_GND1  5011  [Keystone5011]  (value not drawn)
TP_GND2  5011  [Keystone5011]  (value not drawn)
TP_GND3  5011  [Keystone5011]  (value not drawn)
U7  TPS1HA08AQPWPRQ1  [TPS1HA08-Q1_N]
U8  TPS1HA08AQPWPRQ1  [TPS1HA08-Q1_N]

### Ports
+3.3V, +12V, DIA_EN(1), DIA_EN(2), EN(1), EN(2), SEL1, SEL2, SNS (out), ST1_GPIO, ST(1), ST(2), VOUT(1), VOUT(2)

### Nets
GND: C7.1 C8.1 C9.2 C10.1 C11.1 D0.3(K) R2.1 R4.1 TP_GND1.1 TP_GND2.1 TP_GND3.1 U7.3(LATCH) U8.3(LATCH)  [also labelled LATCH1_IC, LATCH2_IC]
+3.3V: R32.2 R33.2 ; port +3.3V
DIA_EN(1): DIA_EN(1).1 R14.1 ; port DIA_EN(1)
DIA_EN(1)_IC: R14.2 U8.16(DIA_EN)
DIA_EN(2): DIA_EN(2).1 R8.1 ; port DIA_EN(2)
DIA_EN(2)_IC: R8.2 U7.16(DIA_EN)
EN(1): EN(1).1 R13.1 ; port EN(1)
EN(1)_IC: R13.2 U8.4(EN)
EN(2): EN(2).1 R7.1 ; port EN(2)
EN(2)_IC: R7.2 U7.4(EN)
SEL1(1)_IC: R15.2 U8.14(SEL1)
SEL1(2)_IC: R9.2 U7.14(SEL1)
SEL2(1)_IC: R16.2 U8.15(SEL2)
SEL2(2)_IC: R10.2 U7.15(SEL2)
SEL_1(1): R9.1 R15.1 SEL1(1).1 SEL1(2).1 ; port SEL1  [also labelled SEL_1(2)]
SEL_2(1): R10.1 R16.1 SEL2(1).1 SEL2(2).1 ; port SEL2  [also labelled SEL_2(2)]
SNS: C9.1 R3.1 SNS_Filter.1 ; port SNS
SNS_IC: R2.2 R3.2 U7.2(SNS) U8.2(SNS)
ST(1): R17.1 ST(1).1 ; port ST(1), port ST1_GPIO
ST(1)_IC: R17.2 R33.1 U8.5(ST)
ST(2): R11.1 ST(2).1 ; port ST(2)
ST(2)_IC: R11.2 R32.1 U7.5(ST)
VBB: C7.2 C8.2 C10.2 C11.2 U7.17(VBB) U8.17(VBB) ; port +12V
VOUT(1): U8.6(VOUT) U8.7(VOUT) U8.8(VOUT) U8.9(VOUT) U8.10(VOUT) U8.11(VOUT) ; port VOUT(1)
VOUT(2): U7.6(VOUT) U7.7(VOUT) U7.8(VOUT) U7.9(VOUT) U7.10(VOUT) U7.11(VOUT) ; port VOUT(2)
NetD0_1: D0.1(A) GND_IC.1 R4.2 U7.1(GND) U8.1(GND)

Not connected (* = marked no-connect by the designer): U7 12(NC)* 13(NC)*; U8 12(NC)* 13(NC)*

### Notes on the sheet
- TPS1HA08 for Seat 1
- TPS1HA08 for Seat 2

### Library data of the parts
C7-C11 = C0805C104M5RACTU: as C15 on sheet TIDA-01184_LED_Drivers
D0 = BAS21-7-F: Diode, Switching, 200V, 0.2A, SOT-23; Manufacturer: Diodes Inc.; U/M: EA; Vf_V: 1.25; Value2: 1.25V; Io_A: 0.2; Vr_V: 200; TJmax_C: 150; RJC_CperW: 500
DIA_EN(1) DIA_EN(2) EN(1) EN(2) GND_IC SEL1(1) SEL1(2) SEL2(1) SEL2(2) ST(1) ST(2) = 5002: Test Point, Miniature, White, TH; Manufacturer: Keystone; CompType: Test Point Loop; U/M: EA
R2 = RC0603FR-072K2L: RES, 2.20 k, 1%, 0.1 W, 0603; Manufacturer: Yageo America; CompType: Resistor; Value: 2.20k; Res_ohm: 2200; Value_Code: 2k20; Tolerance_%: 1; Power_W: 0.1; Value2: 0.1W; VDC_V: 150; TempCo: 200 ppm/C; SizeArea_mm2: 1.28; SizeX_mm: 1.6; SizeY_mm: 0.8; U/M: EA; AEC Category: Q200
R3 R7-R11 R13-R17 = CRCW060310K0JNEA: as R20 on sheet TIDA-01184_LED_Drivers
R4 = RC0603JR-071KL: as R12 on sheet TIDA-01184_LED_Drivers
R32 R33 = RC1608J103CS: RES, 10 k, 5%, 0.1 W, 0603; Manufacturer: Samsung Electro-Mechanics; CompType: Resistor; Value: 10k; Res_ohm: 10000; Value_Code: 10k0; Tolerance_%: 5; Power_W: 0.1; Value2: 0.1W; VDC_V: 31; TempCo: 100 ppm/C; SizeArea_mm2: 1.28; SizeX_mm: 1.6; SizeY_mm: 0.8; SizeZ_mm: 1; EIA_Code: E24; U/M: EA; AEC Category: Q200; AEC Qualified: N
SNS_Filter = 5010: Test Point, Multipurpose, Red, TH; Manufacturer: Keystone; CompType: Test Point Loop; U/M: EA
TP_GND1-TP_GND3 = 5011: Test Point, Multipurpose, Black, TH; Manufacturer: Keystone; CompType: Test Point Loop; U/M: EA
U7 U8 = TPS1HA08CQPWPRQ1: 40-V, 8-mOhm Single-Channel Smart High-Side Switch, TPS1HA08-Q1 (TSSOP-16); Alternate PartNumber: TPS1HA08CQPWPTQ1; Manufacturer: Texas Instruments; SymbolCreator: Altium; SizeArea_mm2: 32; SizeAreaWB_mm2: 58.8; SizeX_mm: 6.4; SizeY_mm: 5; SizeZ_mm: 1.2; CompType: IC; U/M: EA

## Sheet TIDA-01184_Load_Card.SchDoc
size 431 x 279 mm; Date: Not shown in title block; ApprovedBy: Not shown in title block; CheckedBy: Not shown in title block; Author: Not shown in title block; CompanyName: Not shown in title block; Engineer: Not shown in title block; Organization: Not shown in title block; Address1: Not shown in title block; Address2: Not shown in title block; Address3: Not shown in title block; Address4: Not shown in title block; DocumentNumber: 1; Revision: Use project parameter SCH_Rev; SheetNumber: 2; SheetTotal: 3; PageSetup: Record=PageOptions¦CenterHorizontal=True¦CenterVertical=True¦PrintScale=1.00¦XCorrection=1.00¦YCorrection=1.00¦PrintKind=0¦BorderSize=5000000¦LeftOffset=0¦BottomOffset=0¦Orientation=2¦PaperLength=1000¦PaperWidth=1000¦Scale=100¦PaperSource=15¦PrintQuality=600¦MediaType=1¦DitherType=10¦PaperKind=Letter¦PrintScaleMode=1
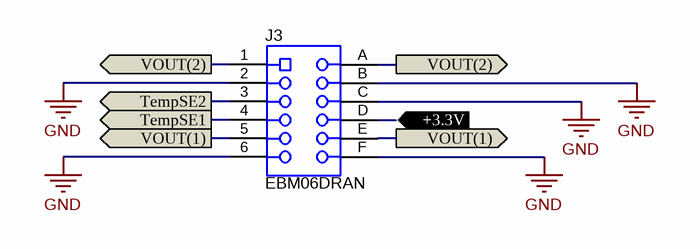
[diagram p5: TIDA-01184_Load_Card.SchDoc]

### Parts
J3  EBM06DRAN  [Sullins_xxM06DRAN]

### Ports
+3.3V (in), TempSE1 (out), TempSE2 (out), VOUT(1) (out), VOUT(2) (out)

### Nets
GND: J3.2 J3.6 J3.B J3.C J3.F
+3.3V: J3.D ; port +3.3V
TempSE1: J3.4 ; port TempSE1
TempSE2: J3.3 ; port TempSE2
VOUT(1): J3.5 J3.E ; port VOUT(1)
VOUT(2): J3.1 J3.A ; port VOUT(2)

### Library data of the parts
J3 = EBM06DRAN: Female Card Edge, 3.96mm, 6x2, Gold, R/A, TH; Manufacturer: Sullins Connector Solutions; SymbolCreator: Altium; CompType: Connector; Pitch_mm: 3.96; Row_Count: 2; Current_A: 3; Voltage_V: 1800; Cert_UL: Y

## Sheet TIDA-01184_Power.SchDoc
size 431 x 279 mm; Date: Not shown in title block; ApprovedBy: Not shown in title block; CheckedBy: Not shown in title block; Author: Not shown in title block; CompanyName: Not shown in title block; DrawnBy: Samip Shah; Engineer: Not shown in title block; Organization: Not shown in title block; Address1: Not shown in title block; Address2: Not shown in title block; Address3: Not shown in title block; Address4: Not shown in title block; DocumentNumber: 1; Revision: Use project parameter SCH_Rev; SheetNumber: 2; SheetTotal: 3; PageSetup: Record=PageOptions¦CenterHorizontal=True¦CenterVertical=True¦PrintScale=1.00¦XCorrection=1.00¦YCorrection=1.00¦PrintKind=0¦BorderSize=5000000¦LeftOffset=0¦BottomOffset=0¦Orientation=2¦PaperLength=1000¦PaperWidth=1000¦Scale=100¦PaperSource=15¦PrintQuality=600¦MediaType=1¦DitherType=10¦PaperKind=Letter¦PrintScaleMode=1
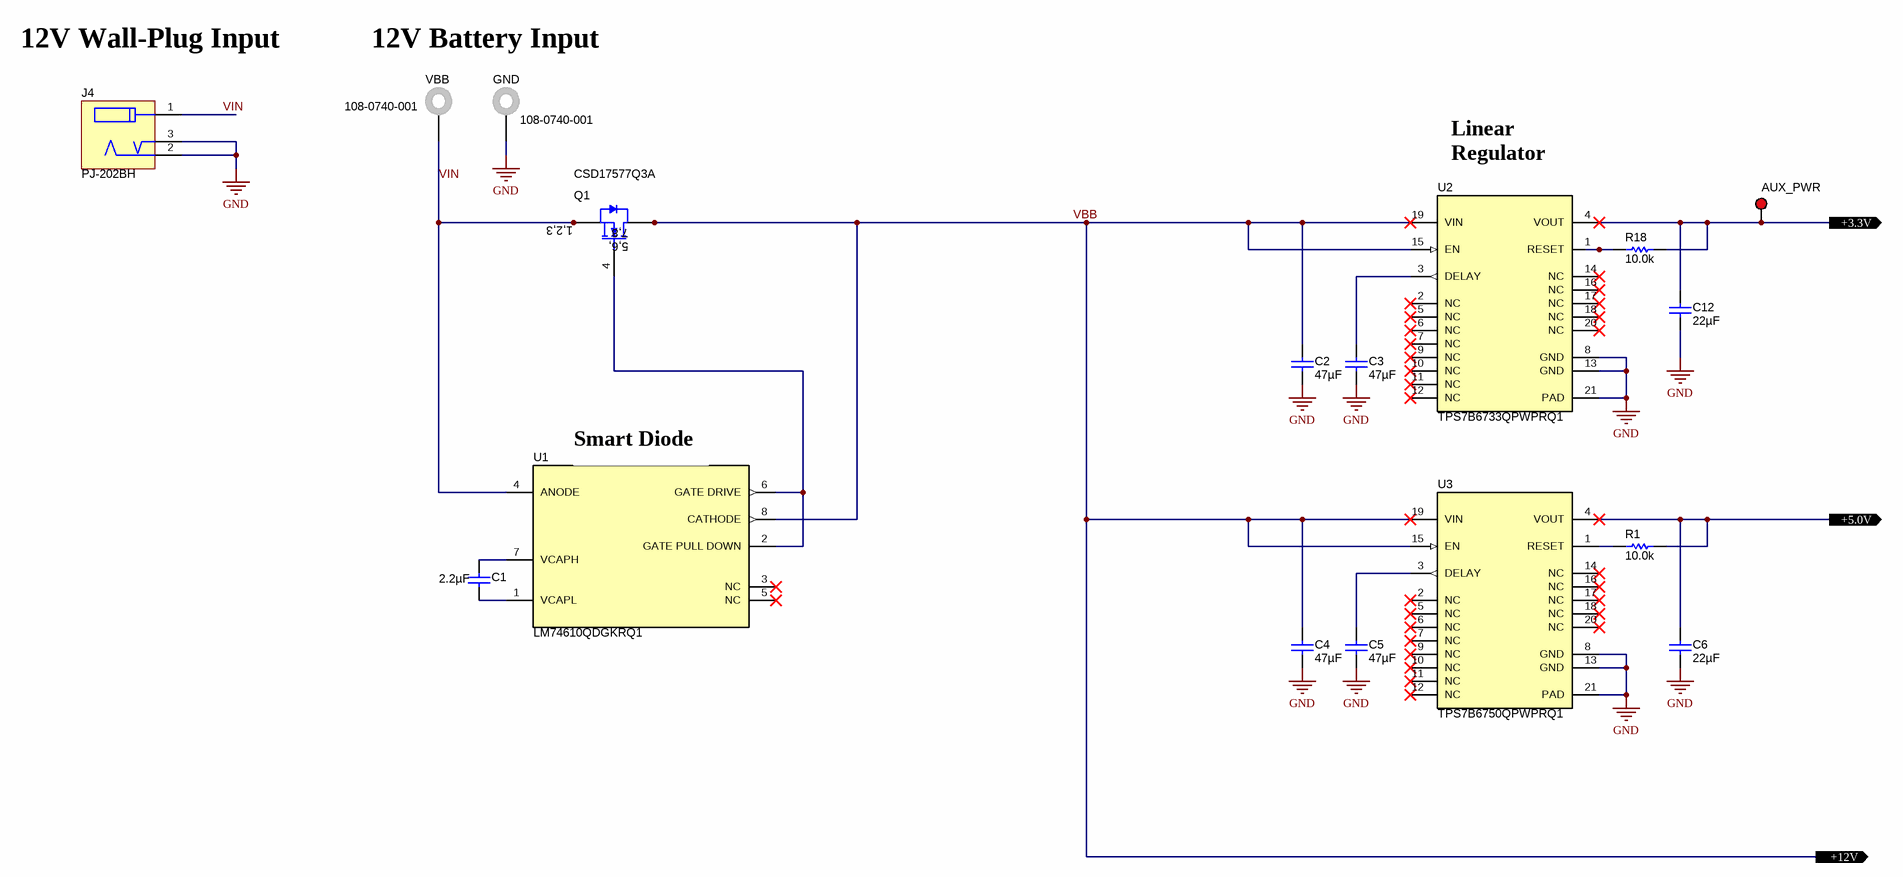
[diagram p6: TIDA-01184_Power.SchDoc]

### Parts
AUX_PWR  5010  [Keystone5010]  (value not drawn)
C1  ValueDisplayed: 2.2µF  [0805_HV]  (hidden comment: C0805C104M5RACTU)
C2  ValueDisplayed: 47µF  [0805_HV]  (hidden comment: C0805C104M5RACTU)
C3  ValueDisplayed: 47µF  [0805_HV]  (hidden comment: C0805C104M5RACTU)
C4  ValueDisplayed: 47µF  [0805_HV]  (hidden comment: C0805C104M5RACTU)
C5  ValueDisplayed: 47µF  [0805_HV]  (hidden comment: C0805C104M5RACTU)
C6  ValueDisplayed: 22µF  [0805_HV]  (hidden comment: C0805C104M5RACTU)
C12  ValueDisplayed: 22µF  [0805_HV]  (hidden comment: C0805C104M5RACTU)
GND  108-0740-001  [Johnson_108-0740-001]
J4  PJ-202BH  [CUI_PJ-202BH]
Q1  CSD17577Q3A  [TRANS_NexFET_Q3A]
R1  ValueDisplayed: 10.0k  [0603]  (hidden comment: RC0603JR-071KL)
R18  ValueDisplayed: 10.0k  [0603]  (hidden comment: RC0603JR-071KL)
U1  LM74610QDGKRQ1  [DGK0008A_N]
U2  TPS7B6733QPWPRQ1  [PWP0020D_L]
U3  TPS7B6750QPWPRQ1  [PWP0020D_M]
VBB  108-0740-001  [Johnson_108-0740-001]

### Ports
+3.3V (out), +5.0V (out), +12V (out)

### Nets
GND: C2.2 C3.2 C4.2 C5.2 C6.2 C12.2 GND.1 J4.2 J4.3 U2.8(GND) U2.13(GND) U2.21(PAD) U3.8(GND) U3.13(GND) U3.21(PAD)
+3.3V: AUX_PWR.1 C12.1 R18.1 U2.4(VOUT) ; port +3.3V
+5.0V: C6.1 R1.1 U3.4(VOUT) ; port +5.0V
VBB: C2.1 C4.1 Q1.5(D) Q1.6(D) Q1.7(D) Q1.8(D) Q1.9(D) U1.8(CATHODE) U2.15(EN) U2.19(VIN) U3.15(EN) U3.19(VIN) ; port +12V
VIN: J4.1 Q1.1(S) Q1.2(S) Q1.3(S) U1.4(ANODE) VBB.1
NetC1_1: C1.1 U1.7(VCAPH)
NetC1_2: C1.2 U1.1(VCAPL)
NetC3_1: C3.1 U2.3(DELAY)
NetC5_1: C5.1 U3.3(DELAY)
NetQ1_4: Q1.4(G) U1.2(GATE_PULL_DOWN) U1.6(GATE_DRIVE)
NetR1_2: R1.2 U3.1(RESET)
NetR18_2: R18.2 U2.1(RESET)

Not connected (* = marked no-connect by the designer): U1 3(NC)* 5(NC)*; U2 2(NC)* 5(NC)* 6(NC)* 7(NC)* 9(NC)* 10(NC)* 11(NC)* 12(NC)* 14(NC)* 16(NC)* 17(NC)* 18(NC)* 20(NC)*; U3 2(NC)* 5(NC)* 6(NC)* 7(NC)* 9(NC)* 10(NC)* 11(NC)* 12(NC)* 14(NC)* 16(NC)* 17(NC)* 18(NC)* 20(NC)*

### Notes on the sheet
- 12V Wall-Plug Input
- 12V Battery Input
- Linear Regulator
- (near U1) Smart Diode

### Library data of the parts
AUX_PWR = 5010: as SNS_Filter on sheet TIDA-01184_HighSideDrivers
C1 = C0805C104M5RACTU: CAP, CERM, 0.1 µF, 50 V, +/- 20%, X7R, 0805; Manufacturer: Kemet; Polarized: N; CompType: Capacitor; Value: 0.1uF; U/M: EA; Cap_F: 0.0000001; Tolerance_%: 20; ESR_ohm: 0.064; Value1: 0.064 ohm; VDC_V: 50; Value2: 50V; IRMS_A: 1.64; TaMin_C: -55; TaMax_C: 125; Cap_Case: 0805
C2-C6 C12 = C0805C104M5RACTU: as C15 on sheet TIDA-01184_LED_Drivers
GND VBB = 108-0740-001: Standard Banana Jack, Uninsulated, 15A; Manufacturer: Emerson Network Power; SymbolCreator: a0412235; CompType: Connector; U/M: EA
J4 = PJ-202BH: Connector, DC Jack 2.5 mm Center Pin, TH; Manufacturer: CUI Inc.; SymbolCreator: a0799628; CompType: Power Jack
Q1 = CSD17577Q3A: MOSFET, N-CH, 30 V, 19 A, SON 3.3x3.3mm; Manufacturer: Texas Instruments; Alternate Manufacturer: None; U/M: EA; ChType: N; Value: 30V; VdsMax_V: 30; Value1: 0.0064 ohm; Rdson45_ohm: 0.0064; Value2: 13 nC; QgTyp_nC: 13; Vgs_V: 20; IdsMax_A: 19; SizeAreaWB_mm2: 18.49; SizeArea_mm2: 10.89; SizeX_mm: 3.3; SizeZ_mm: 0.9; AEC Category: Q101
R1 R18 = RC0603JR-071KL: as R12 on sheet TIDA-01184_LED_Drivers
U1 = LM74610QDGKRQ1: Smart Diode Controller, DGK0008A; Manufacturer: Texas Instruments; SymbolCreator: Altium; SizeArea_mm2: 15.655; SizeAreaWB_mm2: 35.955; SizeX_mm: 5.05; SizeY_mm: 3.1; SizeZ_mm: 1.1; CompType: IC; U/M: EA
U2 = TPS7B6733QPWPRQ1: Automotive 450-mA High-Voltage Ultra-Low IQ Low-Dropout Regulator, PWP0020D (TSSOP-20); Manufacturer: Texas Instruments; SymbolCreator: Altium; SizeArea_mm2: 41.6; SizeAreaWB_mm2: 71.4; SizeX_mm: 6.4; SizeY_mm: 6.5; SizeZ_mm: 1.2; CompType: IC; U/M: EA
U3 = TPS7B6750QPWPRQ1: 450-mA High-Voltage Ultra-Low IQ Low-Dropout Regulator, PWP0020D; Manufacturer: Texas Instruments; SymbolCreator: Altium; SizeArea_mm2: 41.6; SizeAreaWB_mm2: 71.4; SizeX_mm: 6.4; SizeY_mm: 6.5; SizeZ_mm: 1.2; CompType: IC; U/M: EA

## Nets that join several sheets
GND: TIDA-01184_LED_Drivers (22 pins), TIDA-01184_Digital (19 pins), TIDA-01184_HighSideDrivers (13 pins), TIDA-01184_Load_Card (5 pins), TIDA-01184_Power (15 pins)
+3.3V: TIDA-01184_Digital (12 pins), TIDA-01184_HighSideDrivers (R32.2 R33.2), TIDA-01184_Load_Card (J3.D), TIDA-01184_Power (AUX_PWR.1 C12.1 R18.1 U2.4)
+5.0V: TIDA-01184_LED_Drivers (12 pins), TIDA-01184_Power (C6.1 R1.1 U3.4)
DIA_EN(1): TIDA-01184_Digital (U6.6), TIDA-01184_HighSideDrivers (DIA_EN(1).1 R14.1)
DIA_EN(2): TIDA-01184_Digital (U6.7), TIDA-01184_HighSideDrivers (DIA_EN(2).1 R8.1)
EN(1): TIDA-01184_Digital (D11.1 J2.2), TIDA-01184_HighSideDrivers (EN(1).1 R13.1)
EN(2): TIDA-01184_Digital (D13.1 J2.1), TIDA-01184_HighSideDrivers (EN(2).1 R7.1)
Encoder_L_A: TIDA-01184_LED_Drivers (C16.1 R20.2), TIDA-01184_Digital (J1.8)
Encoder_L_B: TIDA-01184_LED_Drivers (C15.1 R21.2), TIDA-01184_Digital (J2.9)
Encoder_R_A: TIDA-01184_LED_Drivers (C18.1 R24.2), TIDA-01184_Digital (J2.8)
Encoder_R_B: TIDA-01184_LED_Drivers (C17.1 R25.2), TIDA-01184_Digital (J2.3)
SCL: TIDA-01184_LED_Drivers (U12.26), TIDA-01184_Digital (J2.4 R27.1 U6.14)
SDA: TIDA-01184_LED_Drivers (U12.27), TIDA-01184_Digital (J2.5 R28.1 U6.15)
SEL_1(1): TIDA-01184_Digital (U6.9), TIDA-01184_HighSideDrivers (R9.1 R15.1 SEL1(1).1 SEL1(2).1)
SEL_2(1): TIDA-01184_Digital (U6.10), TIDA-01184_HighSideDrivers (R10.1 R16.1 SEL2(1).1 SEL2(2).1)
SNS: TIDA-01184_Digital (J1.4), TIDA-01184_HighSideDrivers (C9.1 R3.1 SNS_Filter.1)
ST(1): TIDA-01184_Digital (D12.2 U6.4), TIDA-01184_HighSideDrivers (R17.1 ST(1).1)
ST(2): TIDA-01184_Digital (D14.2), TIDA-01184_HighSideDrivers (R11.1 ST(2).1)
TempSE1: TIDA-01184_Digital (J1.3), TIDA-01184_Load_Card (J3.4)
TempSE2: TIDA-01184_Digital (J1.2), TIDA-01184_Load_Card (J3.3)
VBB: TIDA-01184_HighSideDrivers (6 pins), TIDA-01184_Power (12 pins)
VOUT(1): TIDA-01184_HighSideDrivers (6 pins), TIDA-01184_Load_Card (J3.5 J3.E)
VOUT(2): TIDA-01184_HighSideDrivers (6 pins), TIDA-01184_Load_Card (J3.1 J3.A)

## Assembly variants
001: not fitted FID1 FID2 FID3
